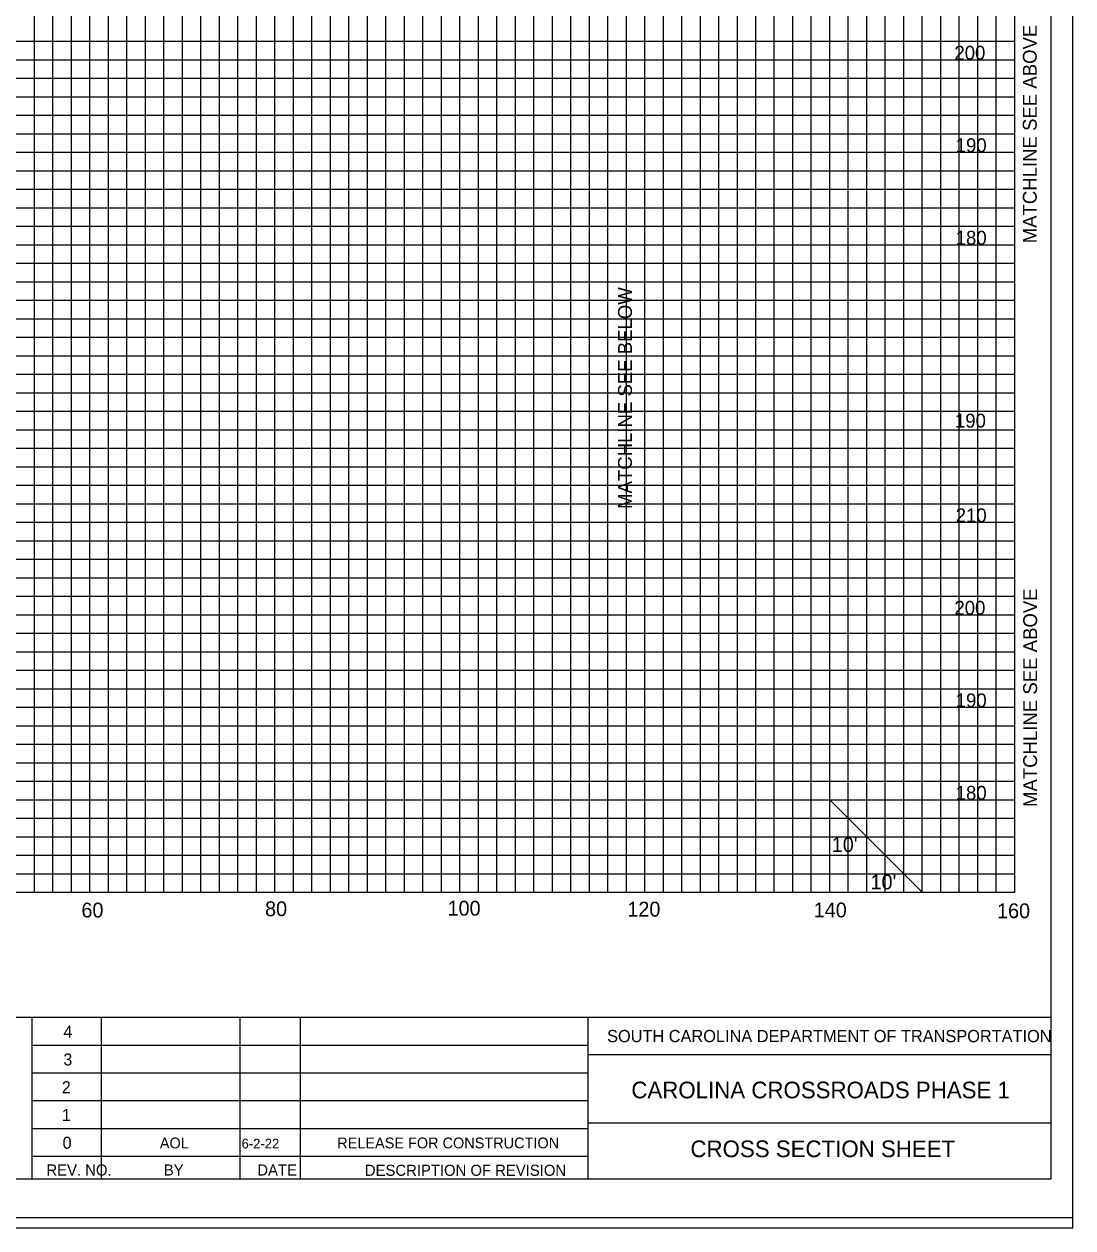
# Model space of a CAD drawing. Extents: x 967 to 1746, y 964 to 7904.
# Drawn here: x 1212.9 to 1326.3, y 4323.7 to 4453.8 of the extents above; entities that cross this region are included whole.
import ezdxf

# ---------------------------------------------------------------- set-up
doc = ezdxf.new("R2010")
doc.units = 0
for name, color, linetype in [('Default', 7, 'Continuous'), ('RD_SHT_Bndy', 7, 'Continuous'), ('RD_SHT_IplotShp', 7, 'Continuous'), ('RD_SHT_Misc1', 7, 'Continuous'), ('RD_SHT_MjGrid', 7, 'Continuous'), ('RD_SHT_MnGrid', 7, 'Continuous'), ('RD_SHT_TX', 7, 'Continuous'), ('RD_Sketch1', 7, 'Continuous'), ('RD_XS_TX_Station', 7, 'Continuous')]:
    doc.layers.add(name, color=color, linetype=linetype)

msp = doc.modelspace()

# ---------------------------------------------------------------- linework, layer by layer
at = {"layer": 'RD_SHT_Bndy'}
for p, q in [((1323.89, 4538.46), (1323.89, 4328.98)), ((996.11, 4346.49), (1323.89, 4346.49)), ((1213.76, 4328.94), (1213.76, 4346.49)), ((1221.26, 4328.95), (1221.26, 4346.48)), ((1236.26, 4328.95), (1236.26, 4346.48)), ((1242.76, 4328.95), (1242.76, 4346.48)), ((1273.88, 4328.98), (1273.88, 4346.49)), ((1213.76, 4343.48), (1273.88, 4343.48)), ((1323.93, 4342.43), (1273.88, 4342.43)), ((1213.76, 4340.48), (1273.88, 4340.48)), ((1213.76, 4337.48), (1273.88, 4337.48)), ((1323.89, 4335.04), (1273.88, 4335.04)), ((1213.76, 4334.48), (1273.88, 4334.48)), ((1213.76, 4331.48), (1273.88, 4331.48)), ((1323.89, 4328.98), (996.11, 4328.98))]:
    msp.add_line(p, q, dxfattribs=at)
at = {"layer": 'RD_SHT_IplotShp'}
for points in [[(967.41, 4323.72), (1326.28, 4323.72), (1326.28, 4543.72), (967.41, 4543.72)], [(988.52, 4324.84), (1326.28, 4324.84), (1326.28, 4542.6), (988.52, 4542.6)]]:
    msp.add_lwpolyline(points, close=True, dxfattribs=at)
at = {"layer": 'RD_SHT_MjGrid'}
for p, q in [((1220, 4360), (1220, 4530)), ((1230, 4360), (1230, 4530)), ((1240, 4360), (1240, 4530)), ((1250, 4360), (1250, 4530)), ((1260, 4360), (1260, 4530)), ((1270, 4360), (1270, 4530)), ((1280, 4360), (1280, 4530)), ((1290, 4360), (1290, 4530)), ((1300, 4360), (1300, 4530)), ((1310, 4360), (1310, 4530)), ((1320, 4360), (1320, 4530)), ((1000, 4450), (1320, 4450)), ((1000, 4440), (1320, 4440)), ((1000, 4430), (1320, 4430)), ((1000, 4420), (1320, 4420)), ((1000, 4410), (1320, 4410)), ((1000, 4400), (1320, 4400)), ((1000, 4390), (1320, 4390)), ((1000, 4380), (1320, 4380)), ((1000, 4370), (1320, 4370)), ((1000, 4360), (1320, 4360))]:
    msp.add_line(p, q, dxfattribs=at)
at = {"layer": 'RD_SHT_MnGrid'}
for p, q in [((1214, 4360), (1214, 4530)), ((1216, 4360), (1216, 4530)), ((1218, 4360), (1218, 4530)), ((1222, 4360), (1222, 4530)), ((1224, 4360), (1224, 4530)), ((1226, 4360), (1226, 4530)), ((1228, 4360), (1228, 4530)), ((1232, 4360), (1232, 4530)), ((1234, 4360), (1234, 4530)), ((1236, 4360), (1236, 4530)), ((1238, 4360), (1238, 4530)), ((1242, 4360), (1242, 4530)), ((1244, 4360), (1244, 4530)), ((1246, 4360), (1246, 4530)), ((1248, 4360), (1248, 4530)), ((1252, 4360), (1252, 4530)), ((1254, 4360), (1254, 4530)), ((1256, 4360), (1256, 4530)), ((1258, 4360), (1258, 4530)), ((1262, 4360), (1262, 4530)), ((1264, 4360), (1264, 4530)), ((1266, 4360), (1266, 4530)), ((1268, 4360), (1268, 4530)), ((1272, 4360), (1272, 4530)), ((1274, 4360), (1274, 4530)), ((1276, 4360), (1276, 4530)), ((1278, 4360), (1278, 4530)), ((1282, 4360), (1282, 4530)), ((1284, 4360), (1284, 4530)), ((1286, 4360), (1286, 4530)), ((1288, 4360), (1288, 4530)), ((1292, 4360), (1292, 4530)), ((1294, 4360), (1294, 4530)), ((1296, 4360), (1296, 4530)), ((1298, 4360), (1298, 4530)), ((1302, 4360), (1302, 4530)), ((1304, 4360), (1304, 4530)), ((1306, 4360), (1306, 4530)), ((1308, 4360), (1308, 4530)), ((1312, 4360), (1312, 4530)), ((1314, 4360), (1314, 4530)), ((1316, 4360), (1316, 4530)), ((1318, 4360), (1318, 4530)), ((1000, 4452), (1320, 4452)), ((1000, 4448), (1320, 4448)), ((1000, 4446), (1320, 4446)), ((1000, 4444), (1320, 4444)), ((1000, 4442), (1320, 4442)), ((1000, 4438), (1320, 4438)), ((1000, 4436), (1320, 4436)), ((1000, 4434), (1320, 4434)), ((1000, 4432), (1320, 4432)), ((1000, 4428), (1320, 4428)), ((1000, 4426), (1320, 4426)), ((1000, 4424), (1320, 4424)), ((1000, 4422), (1320, 4422)), ((1000, 4418), (1320, 4418)), ((1000, 4416), (1320, 4416)), ((1000, 4414), (1320, 4414)), ((1000, 4412), (1320, 4412)), ((1000, 4408), (1320, 4408)), ((1000, 4406), (1320, 4406)), ((1000, 4404), (1320, 4404)), ((1000, 4402), (1320, 4402)), ((1000, 4398), (1320, 4398)), ((1000, 4396), (1320, 4396)), ((1000, 4394), (1320, 4394)), ((1000, 4392), (1320, 4392)), ((1000, 4388), (1320, 4388)), ((1000, 4386), (1320, 4386)), ((1000, 4384), (1320, 4384)), ((1000, 4382), (1320, 4382)), ((1000, 4378), (1320, 4378)), ((1000, 4376), (1320, 4376)), ((1000, 4374), (1320, 4374)), ((1000, 4372), (1320, 4372)), ((1000, 4368), (1320, 4368)), ((1000, 4366), (1320, 4366)), ((1000, 4364), (1320, 4364)), ((1000, 4362), (1320, 4362))]:
    msp.add_line(p, q, dxfattribs=at)
at = {"layer": 'RD_SHT_TX'}
msp.add_line((1300, 4370), (1310, 4360), dxfattribs=at)
at = {"layer": 'RD_Sketch1'}
msp.add_lwpolyline([(967.41, 4323.72), (1326.28, 4323.72), (1326.28, 4543.72), (967.41, 4543.72)], close=True, dxfattribs=at)
at = {"layer": 'RD_XS_TX_Station'}
msp.add_line((1280, 4400), (1280, 4433.91), dxfattribs=at)

# ---------------------------------------------------------------- texts
at = {"layer": 'Default'}
for s, p in [('200', (1313.47, 4450)), ('190', (1313.61, 4440)), ('180', (1313.61, 4430)), ('190', (1313.53, 4410.23)), ('210', (1313.61, 4400)), ('200', (1313.47, 4390)), ('190', (1313.61, 4380)), ('180', (1313.61, 4370))]:
    msp.add_text(s, height=1.5, dxfattribs=at).set_placement(p)
at = {"layer": 'RD_SHT_Misc1'}
for s, height, p in [('AOL', 1.17, (1227.56, 4332.32)), ('6-2-22', 1.053, (1236.4, 4332.31)), ('RELEASE FOR CONSTRUCTION', 1.17, (1246.74, 4332.32))]:
    msp.add_text(s, height=height, dxfattribs=at).set_placement(p)
at = {"layer": 'RD_SHT_TX'}
for s, height, p in [("10'", 1.6, (1300.21, 4364.36)), ("10'", 1.6, (1304.4, 4360.32)), ('60', 1.6, (1219.08, 4357.28)), ('80', 1.6, (1238.94, 4357.42)), ('100', 1.6, (1258.67, 4357.48)), ('120', 1.6, (1278.11, 4357.38)), ('140', 1.6, (1298.26, 4357.29)), ('160', 1.6, (1318.08, 4357.2)), ('4', 1.3, (1217.13, 4344.28)), ('SOUTH CAROLINA DEPARTMENT OF TRANSPORTATION', 1.32, (1275.92, 4343.8)), ('3', 1.3, (1217.13, 4341.28)), ('2', 1.3, (1216.97, 4338.28)), ('1', 1.3, (1216.97, 4335.28)), ('0', 1.3, (1217.05, 4332.28)), ('REV. NO.', 1.2, (1215.3, 4329.38)), ('BY', 1.2, (1227.99, 4329.38)), ('DATE', 1.2, (1238.1, 4329.38)), ('DESCRIPTION OF REVISION', 1.2, (1249.73, 4329.35))]:
    msp.add_text(s, height=height, dxfattribs=at).set_placement(p)
for s, p in [('CAROLINA CROSSROADS PHASE 1', (1278.54, 4337.73)), ('CROSS SECTION SHEET', (1284.93, 4331.37))]:
    msp.add_text(s, height=1.8, rotation=0, dxfattribs=at).set_placement(p)
at = {"layer": 'RD_XS_TX_Station'}
for s, p in [('MATCHLINE SEE ABOVE', (1322.37, 4430.15)), ('MATCHLINE SEE BELOW', (1278.6, 4401.44)), ('MATCHLINE SEE ABOVE', (1322.41, 4369.22))]:
    msp.add_text(s, height=1.5, rotation=90, dxfattribs=at).set_placement(p)

doc.saveas('drawing.dxf')
